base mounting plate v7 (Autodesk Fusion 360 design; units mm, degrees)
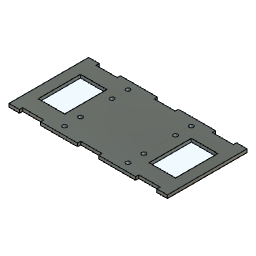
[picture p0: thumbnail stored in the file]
sketch "Sketch1" plane through (0, 0, 0) normal (0, 0, 1) x axis (1, 0, 0)
  line L1 (85, 0) -> (0, 0)
  line L2 (85, 75.5) -> (85, 0)
  line L3 (0, 75.5) -> (85, 75.5)
  line L4 (0, 0) -> (0, 75.5)
  point P1 (0, 0)
  point P2 (0, 0)
  point P4 (85, 75.5)
  point P5 (0, 75.5)
  point P3 (85, 0)
  horizontal L1
  vertical L2
  horizontal L3
  vertical L4
  coincident P1 P2
  dimension "d1" distance P4 P5 = 85
  dimension "d2" distance P3 P4 = 75.5
extrude "Extrude1" new body sketch "Sketch1" along normal blind 3
hole "Hole1" HoleDepth 3 HoleDiameter 4 TipAngle 118
rectangular_pattern "R-Pattern1" uSpaceDistance 0 vSpaceDistance 15
work_plane "WorkPlane1"
mirror "Mirror1"
work_plane "WorkPlane3"
mirror "Mirror2"
extrude "Extrude2" add of existing geometry blind 32.5
extrude "Extrude3" add of existing geometry blind 32.5
sketch "Sketch3" plane through (0, 0, 3) normal (0, 0, 1) x axis (-1, 0, 0)
  line L1 (-117.5, 0) -> (32.5, 0)
  line L2 (-117.5, -75.5) -> (-117.5, 0)
  line L3 (32.5, -75.5) -> (-117.5, -75.5)
  line L4 (32.5, 0) -> (32.5, -75.5)
  line L5 (2.5, -75.5) -> (22.5, -75.5)
  line L6 (2.5, -72.5) -> (2.5, -75.5)
  line L7 (22.5, -72.5) -> (2.5, -72.5)
  line L8 (22.5, -75.5) -> (22.5, -72.5)
  line L9 (-52.5, -75.5) -> (-32.5, -75.5)
  line L10 (-52.5, -72.5) -> (-52.5, -75.5)
  line L11 (-32.5, -72.5) -> (-52.5, -72.5)
  line L12 (-32.5, -75.5) -> (-32.5, -72.5)
  line L13 (-107.5, -75.5) -> (-87.5, -75.5)
  line L14 (-107.5, -72.5) -> (-107.5, -75.5)
  line L15 (-87.5, -72.5) -> (-107.5, -72.5)
  line L16 (-87.5, -75.5) -> (-87.5, -72.5)
  line L17 (-87.5, -74) -> (-52.5, -74)
  line L18 (-32.5, -74) -> (2.5, -74)
  circle C1 centre (-12.5, -52.75) radius 2
  circle C2 centre (-12.5, -67.75) radius 2
  circle C3 centre (-12.5, -22.75) radius 2
  circle C4 centre (-12.5, -7.75) radius 2
  circle C5 centre (-72.5, -22.75) radius 2
  circle C6 centre (-72.5, -7.75) radius 2
  circle C7 centre (-72.5, -52.75) radius 2
  circle C8 centre (-72.5, -67.75) radius 2
  point P14 (22.5, -75.5)
  point P18 (-32.5, -75.5)
  point P22 (-87.5, -75.5)
  point P26 (-52.5, -74)
  point P27 (-87.5, -74)
  point P28 (2.5, -74)
  point P29 (-32.5, -74)
  point P15 (2.5, -75.5)
  point P23 (-107.5, -75.5)
  horizontal L5
  vertical L6
  horizontal L7
  vertical L8
  coincident L3 P14
  horizontal L9
  vertical L10
  horizontal L11
  vertical L12
  coincident L3 P18
  horizontal L13
  vertical L14
  horizontal L15
  vertical L16
  coincident L3 P22
  equal L8 L12
  equal L12 L16
  midpoint L10 P26
  midpoint L16 P27
  midpoint L6 P28
  midpoint L12 P29
  equal L17 L18
  dimension "d21" distance L4 L8 = 10
  dimension "d22" distance L5 L7 = 3
  dimension "d23" distance P14 P15 = 20
  dimension "d25" distance L2 L14 = 10
  dimension "d27" distance P22 P23 = 20
  dimension "d28" distance L10 L12 = 20
extrude "Extrude4" cut sketch "Sketch3" profile of L3 L5 L6 L7 L8 L9 L10 L11 L12 L13 L14 L15 L16 to an object
mirror "Mirror3"
sketch "Sketch4" plane through (0, 0, 3) normal (0, 0, 1) x axis (-1, 0, 0)
  line L1 (22.5, -3) -> (22.5, 0)
  line L2 (2.5, -3) -> (22.5, -3)
  line L3 (2.5, 0) -> (2.5, -3)
  line L4 (-32.5, 0) -> (2.5, 0)
  line L5 (-32.5, -3) -> (-32.5, 0)
  line L6 (-52.5, -3) -> (-32.5, -3)
  line L7 (-52.5, 0) -> (-52.5, -3)
  line L8 (-87.5, 0) -> (-52.5, 0)
  line L9 (-87.5, -3) -> (-87.5, 0)
  line L10 (-107.5, -3) -> (-87.5, -3)
  line L11 (-107.5, 0) -> (-107.5, -3)
  line L12 (-117.5, 0) -> (-107.5, 0)
  line L13 (-117.5, -75.5) -> (-117.5, 0)
  line L14 (-107.5, -75.5) -> (-117.5, -75.5)
  line L15 (-107.5, -72.5) -> (-107.5, -75.5)
  line L16 (-87.5, -72.5) -> (-107.5, -72.5)
  line L17 (-87.5, -75.5) -> (-87.5, -72.5)
  line L18 (-52.5, -75.5) -> (-87.5, -75.5)
  line L19 (-52.5, -72.5) -> (-52.5, -75.5)
  line L20 (-32.5, -72.5) -> (-52.5, -72.5)
  line L21 (-32.5, -75.5) -> (-32.5, -72.5)
  line L22 (2.5, -75.5) -> (-32.5, -75.5)
  line L23 (2.5, -72.5) -> (2.5, -75.5)
  line L24 (22.5, -72.5) -> (2.5, -72.5)
  line L25 (22.5, -75.5) -> (22.5, -72.5)
  line L26 (32.5, -75.5) -> (22.5, -75.5)
  line L27 (32.5, 0) -> (32.5, -75.5)
  line L28 (22.5, 0) -> (32.5, 0)
  circle C1 centre (-72.5, -67.75) radius 2
  circle C2 centre (-72.5, -52.75) radius 2
  circle C3 centre (-72.5, -7.75) radius 2
  circle C4 centre (-72.5, -22.75) radius 2
  circle C5 centre (-12.5, -7.75) radius 2
  circle C6 centre (-12.5, -22.75) radius 2
  circle C7 centre (-12.5, -67.75) radius 2
  circle C8 centre (-12.5, -52.75) radius 2
sketch "Sketch5" plane through (0, 0, 3) normal (0, 0, 1) x axis (1, 0, 0)
  line L1 (-32.5, 0) -> (-32.5, 75.5)
  line L2 (117.5, 75.5) -> (117.5, 0)
  line L3 (87.5, 0) -> (52.5, 0)
  line L4 (52.5, 75.5) -> (87.5, 75.5)
  line L5 (-32.5, 37.75) -> (117.5, 37.75)
  line L6 (32.5, 0) -> (-2.5, 0)
  line L7 (-22.5, 3) -> (-22.5, 0)
  line L8 (-2.5, 3) -> (-22.5, 3)
  line L9 (-2.5, 0) -> (-2.5, 3)
  line L10 (32.5, 0) -> (-2.5, 0)
  line L11 (32.5, 3) -> (32.5, 0)
  line L12 (52.5, 3) -> (32.5, 3)
  line L13 (52.5, 0) -> (52.5, 3)
  line L14 (87.5, 0) -> (52.5, 0)
  line L15 (87.5, 3) -> (87.5, 0)
  line L16 (107.5, 3) -> (87.5, 3)
  line L17 (107.5, 0) -> (107.5, 3)
  line L18 (117.5, 0) -> (107.5, 0)
  line L19 (117.5, 75.5) -> (117.5, 0)
  line L20 (107.5, 75.5) -> (117.5, 75.5)
  line L21 (107.5, 72.5) -> (107.5, 75.5)
  line L22 (87.5, 72.5) -> (107.5, 72.5)
  line L23 (87.5, 75.5) -> (87.5, 72.5)
  line L24 (52.5, 75.5) -> (87.5, 75.5)
  line L25 (52.5, 72.5) -> (52.5, 75.5)
  line L26 (32.5, 72.5) -> (52.5, 72.5)
  line L27 (32.5, 75.5) -> (32.5, 72.5)
  line L28 (-2.5, 75.5) -> (32.5, 75.5)
  line L29 (-2.5, 72.5) -> (-2.5, 75.5)
  line L30 (-22.5, 72.5) -> (-2.5, 72.5)
  line L31 (-22.5, 75.5) -> (-22.5, 72.5)
  line L32 (-32.5, 75.5) -> (-22.5, 75.5)
  line L33 (-32.5, 0) -> (-32.5, 75.5)
  line L34 (-22.5, 0) -> (-32.5, 0)
  line L35 (42.5, 72.5) -> (42.5, 3)
  line L36 (107.5, 17.75) -> (82.5, 17.75)
  line L37 (107.5, 57.75) -> (107.5, 17.75)
  line L38 (82.5, 57.75) -> (107.5, 57.75)
  line L39 (82.5, 17.75) -> (82.5, 57.75)
  line L40 (-22.5, 17.75) -> (2.5, 17.75)
  line L41 (-22.5, 57.75) -> (-22.5, 17.75)
  line L42 (2.5, 57.75) -> (-22.5, 57.75)
  line L43 (2.5, 17.75) -> (2.5, 57.75)
  circle C1 centre (72.5, 67.75) radius 2
  circle C2 centre (72.5, 52.75) radius 2
  circle C3 centre (72.5, 7.75) radius 2
  circle C4 centre (72.5, 22.75) radius 2
  circle C5 centre (12.5, 7.75) radius 2
  circle C6 centre (12.5, 22.75) radius 2
  circle C7 centre (12.5, 67.75) radius 2
  circle C8 centre (12.5, 52.75) radius 2
  point P10 (117.5, 37.75)
  point P11 (-32.5, 37.75)
  point P50 (42.5, 3)
  point P51 (42.5, 72.5)
  point P56 (2.5, 17.75)
  point P57 (-22.5, 17.75)
  midpoint L2 P10
  midpoint L1 P11
  midpoint L12 P50
  midpoint L26 P51
  horizontal L36
  vertical L37
  horizontal L38
  vertical L39
  horizontal L40
  vertical L41
  horizontal L42
  vertical L43
  equal L36 L40
  symmetric L35 L39 L43
  equal L39 L43
  symmetric L5 L36 L38
  symmetric L5 L40 L42
  dimension "d33" distance P56 P57 = 25
  dimension "d34" distance L40 L42 = 40
  dimension "d37" distance L37 L41 = 130
extrude "Extrude5" cut sketch "Sketch5" profile of L36 L37 L38 L39 L40 L41 L42 L43 to an object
